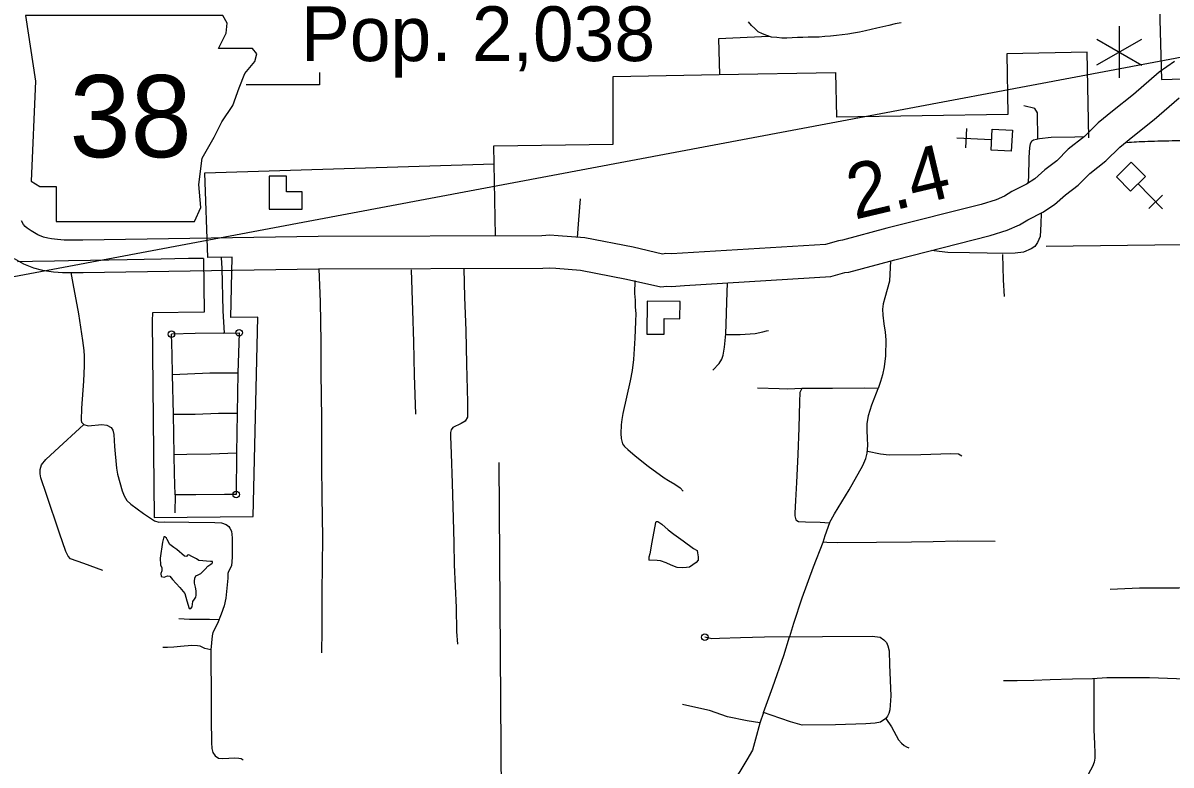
# Model space of a CAD drawing. Extents: x 1367863 to 1368197, y 380048 to 380261.
# Drawn here: x 1367977.76 to 1368012.13, y 380109.23 to 380131.45 of the extents above; entities that cross this region are included whole.
import ezdxf

# ---------------------------------------------------------------- set-up
doc = ezdxf.new("R2010")
doc.units = 0
for name, color, linetype in [('Level 10', 7, 'Continuous'), ('Level 21', 7, 'Continuous'), ('Level 31', 7, 'Continuous'), ('Level 32', 7, 'Continuous'), ('Level 33', 7, 'Continuous'), ('Level 35', 7, 'Continuous'), ('Level 45', 7, 'Continuous'), ('Level 48', 7, 'Continuous'), ('Level 5', 7, 'Continuous'), ('Level 57', 7, 'Continuous'), ('Level 58', 7, 'Continuous'), ('Level 6', 7, 'Continuous'), ('R_Draft', 7, 'Continuous')]:
    doc.layers.add(name, color=color, linetype=linetype)

msp = doc.modelspace()

# ---------------------------------------------------------------- linework, layer by layer
at = {"layer": 'Level 10'}
for points in [[(1368011.429, 380151.098), (1368011.439, 380145.66), (1368011.416, 380141.25), (1368011.392, 380140.52), (1368011.431, 380140.222), (1368011.504, 380139.453), (1368011.603, 380138.92), (1368011.693, 380137.345), (1368011.778, 380132.275), (1368011.845, 380129.756)], [(1368012.237, 380130.295), (1368011.777, 380129.977), (1368011.011, 380129.309), (1368010.379, 380128.804), (1368009.956, 380128.455), (1368009.541, 380128.054), (1368009.05, 380127.67), (1368008.714, 380127.325), (1368008.357, 380127.056), (1368008.052, 380126.787), (1368007.803, 380126.619), (1368007.369, 380126.4), (1368007.149, 380126.265), (1368006.894, 380126.155), (1368006.45, 380126.016), (1368003.623, 380125.301), (1368002.292, 380124.945), (1368002.173, 380124.93), (1368001.785, 380124.821), (1367997.501, 380124.556), (1367997.172, 380124.536), (1367997.008, 380124.543), (1367996.908, 380124.532), (1367996.024, 380124.733), (1367994.579, 380125.013), (1367993.778, 380125.078), (1367993.53, 380125.093), (1367993.289, 380125.078), (1367986.594, 380125.055), (1367979.548, 380124.948)], [(1368011.845, 380129.756), (1368012.815, 380129.782)], [(1367979.555, 380123.978), (1367986.603, 380124.084), (1367993.322, 380124.108), (1367993.531, 380124.121), (1367993.709, 380124.11), (1367994.447, 380124.05), (1367995.825, 380123.783), (1367996.853, 380123.55), (1367997.039, 380123.571), (1367997.179, 380123.564), (1367997.561, 380123.588), (1368001.948, 380123.859), (1368002.368, 380123.977), (1368002.481, 380123.991), (1368003.867, 380124.362), (1368006.714, 380125.082), (1368007.231, 380125.244), (1368007.597, 380125.401), (1368007.842, 380125.552), (1368008.295, 380125.78), (1368008.647, 380126.018), (1368008.97, 380126.304), (1368009.357, 380126.594), (1368009.7, 380126.946), (1368010.179, 380127.321), (1368010.603, 380127.731), (1368010.991, 380128.051), (1368011.633, 380128.564), (1368012.373, 380129.209)], [(1367979.548, 380124.948), (1367979.056, 380124.944), (1367978.988, 380124.946), (1367978.886, 380124.952), (1367978.787, 380124.962), (1367978.613, 380124.986), (1367978.505, 380125.007), (1367978.372, 380125.039), (1367978.201, 380125.109), (1367978.003, 380125.223), (1367977.88, 380125.306), (1367977.822, 380125.354), (1367977.772, 380125.411), (1367977.71, 380125.521)], [(1367977.49, 380124.399), (1367977.773, 380124.236), (1367978.071, 380124.114), (1367978.299, 380124.058), (1367978.456, 380124.029), (1367978.674, 380123.998), (1367978.81, 380123.985), (1367978.944, 380123.977), (1367979.046, 380123.974), (1367979.555, 380123.978)]]:
    msp.add_lwpolyline(points, dxfattribs=at)
at = {"layer": 'Level 21'}
msp.add_lwpolyline([(1367977.833, 380131.673), (1367978.129, 380129.704), (1367977.998, 380126.716), (1367978.26, 380126.552), (1367978.753, 380126.552), (1367978.753, 380125.501), (1367982.889, 380125.501), (1367983.086, 380125.928), (1367983.02, 380126.618), (1367983.119, 380127.405), (1367983.48, 380128.029), (1367983.71, 380128.489), (1367984.038, 380128.981), (1367984.235, 380129.507), (1367984.399, 380129.933), (1367984.695, 380130.294), (1367984.76, 380130.524), (1367984.629, 380130.688), (1367983.611, 380130.688), (1367983.841, 380131.148), (1367983.874, 380131.444), (1367983.738, 380131.67)], close=True, dxfattribs=at)
at = {"layer": 'Level 31'}
for points in [[(1368008.15, 380127.984), (1368008.132, 380128.757), (1368008.054, 380128.887), (1368007.725, 380128.965)], [(1368009.527, 380128.043), (1368009.255, 380128.034), (1368008.544, 380128.021), (1368008.195, 380127.985), (1368008.014, 380127.937), (1368007.96, 380127.901), (1368007.912, 380127.829), (1368007.894, 380127.72), (1368007.876, 380127.419), (1368007.87, 380126.834), (1368007.849, 380126.642)], [(1368010.811, 380127.873), (1368010.881, 380127.878), (1368010.954, 380127.883), (1368011.029, 380127.887), (1368011.104, 380127.892), (1368011.181, 380127.897), (1368011.262, 380127.901), (1368011.348, 380127.905), (1368011.44, 380127.909), (1368011.536, 380127.911), (1368011.637, 380127.914), (1368011.743, 380127.918), (1368011.85, 380127.919), (1368011.958, 380127.922), (1368012.065, 380127.924), (1368012.163, 380127.927), (1368012.241, 380127.93), (1368012.29, 380127.93), (1368012.378, 380127.931), (1368012.429, 380127.932), (1368012.441, 380127.932)], [(1368008.247, 380125.756), (1368008.234, 380125.44), (1368008.218, 380125.054), (1368008.138, 380124.872), (1368008.052, 380124.754), (1368007.945, 380124.689), (1368007.714, 380124.587), (1368007.462, 380124.555), (1368007.082, 380124.55), (1368006.626, 380124.555), (1368006.101, 380124.571), (1368005.447, 380124.577), (1368005.195, 380124.609), (1368004.974, 380124.642)], [(1368003.738, 380124.327), (1368003.704, 380123.717), (1368003.559, 380123.217), (1368003.511, 380123.036), (1368003.493, 380122.885), (1368003.499, 380122.698), (1368003.535, 380122.445), (1368003.577, 380122.192), (1368003.589, 380121.963), (1368003.583, 380121.487), (1368003.541, 380121.159), (1368003.493, 380120.912), (1368003.439, 380120.713), (1368003.36, 380120.502)], [(1367979.579, 380119.425), (1367979.517, 380119.492), (1367979.51, 380119.562), (1367979.517, 380119.918), (1367979.579, 380120.721), (1367979.6, 380121.189), (1367979.6, 380121.475), (1367979.593, 380121.642), (1367979.552, 380121.943), (1367979.433, 380122.745), (1367979.258, 380123.646), (1367979.196, 380123.975)], [(1367986.71, 380112.589), (1367986.719, 380113.269), (1367986.719, 380114.397), (1367986.737, 380116.034), (1367986.719, 380117.287), (1367986.71, 380118.186), (1367986.71, 380119.609), (1367986.683, 380120.978), (1367986.683, 380121.897), (1367986.665, 380123.096), (1367986.63, 380124.085)], [(1367989.382, 380124.059), (1367989.418, 380122.838), (1367989.454, 380121.899), (1367989.472, 380120.905), (1367989.508, 380119.733)], [(1367990.958, 380124.099), (1367990.976, 380123.243), (1367991.021, 380122.241), (1367991.039, 380121.238), (1367991.066, 380120.093)], [(1367996.075, 380123.735), (1367996.068, 380123.35), (1367996.086, 380123.148), (1367996.091, 380122.943), (1367996.109, 380122.75), (1367996.095, 380122.513), (1367996.082, 380122.016), (1367996.037, 380121.377), (1367996.001, 380121.044), (1367995.934, 380120.739), (1367995.831, 380120.247), (1367995.715, 380119.755), (1367995.684, 380119.576), (1367995.67, 380119.419), (1367995.661, 380119.155), (1367995.67, 380119.008), (1367995.706, 380118.851), (1367995.764, 380118.771), (1367995.867, 380118.681), (1367996.086, 380118.487), (1367996.475, 380118.182), (1367996.954, 380117.829), (1367997.083, 380117.757), (1367997.28, 380117.641), (1367997.432, 380117.529), (1367997.522, 380117.435)], [(1367998.411, 380121.059), (1367998.599, 380121.252), (1367998.679, 380121.381), (1367998.724, 380121.507), (1367998.76, 380121.744), (1367998.8, 380122.142), (1367998.809, 380122.437), (1367998.831, 380123.086), (1367998.848, 380123.667)], [(1367998.798, 380122.125), (1367999.234, 380122.124), (1367999.685, 380122.151), (1367999.913, 380122.2), (1368000.016, 380122.231), (1368000.083, 380122.24)], [(1368003.36, 380120.502), (1368002.964, 380120.515), (1368002.001, 380120.502), (1368001.079, 380120.502), (1368000.657, 380120.49), (1368000.398, 380120.496), (1367999.748, 380120.515)], [(1368001.079, 380120.502), (1368001.019, 380120.388), (1368001.007, 380120.111), (1368000.989, 380119.333), (1368000.958, 380118.529), (1368000.922, 380117.691), (1368000.892, 380117.155), (1368000.868, 380116.775), (1368000.868, 380116.691), (1368000.898, 380116.576), (1368000.983, 380116.528), (1368001.187, 380116.516), (1368001.627, 380116.504), (1368001.904, 380116.48)], [(1368001.904, 380116.48), (1368002.061, 380116.751), (1368002.495, 380117.474), (1368002.91, 380118.203), (1368002.995, 380118.408), (1368003.031, 380118.571), (1368003.055, 380118.8), (1368003.043, 380119.023), (1368003.031, 380119.252), (1368003.037, 380119.451), (1368003.079, 380119.698), (1368003.175, 380120.017), (1368003.314, 380120.379), (1368003.36, 380120.502)], [(1367991.066, 380120.093), (1367991.066, 380119.649), (1367990.994, 380119.524), (1367990.878, 380119.461), (1367990.628, 380119.336), (1367990.583, 380119.273), (1367990.556, 380119.193), (1367990.556, 380119.076), (1367990.574, 380118.548), (1367990.61, 380117.671), (1367990.637, 380116.624), (1367990.655, 380115.887), (1367990.663, 380115.225), (1367990.726, 380113.954), (1367990.735, 380113.229), (1367990.771, 380112.849)], [(1367980.152, 380115.062), (1367979.579, 380115.272), (1367979.182, 380115.404), (1367979.105, 380115.488), (1367979.042, 380115.628), (1367978.847, 380116.172), (1367978.463, 380117.331), (1367978.295, 380117.827), (1367978.274, 380117.952), (1367978.274, 380118.078), (1367978.309, 380118.218), (1367978.442, 380118.385), (1367978.84, 380118.748), (1367979.447, 380119.307), (1367979.579, 380119.425)], [(1367979.579, 380119.425), (1367979.712, 380119.391), (1367980.117, 380119.425), (1367980.263, 380119.405), (1367980.396, 380119.342), (1367980.452, 380119.258), (1367980.48, 380119.132), (1367980.494, 380118.769), (1367980.556, 380118.12), (1367980.591, 380117.939), (1367980.731, 380117.443), (1367980.787, 380117.296), (1367980.863, 380117.15), (1367980.989, 380117.045), (1367981.366, 380116.766), (1367981.694, 380116.542), (1367981.826, 380116.5), (1367982.008, 380116.514), (1367982.727, 380116.507), (1367983.501, 380116.493), (1367983.697, 380116.48), (1367983.836, 380116.431), (1367983.92, 380116.375), (1367983.955, 380116.326), (1367984.004, 380116.235), (1367984.025, 380116.033), (1367984.025, 380115.809), (1367984.025, 380115.46), (1367983.997, 380115.202), (1367983.913, 380115.027), (1367983.892, 380114.965), (1367983.892, 380114.832), (1367983.829, 380114.225), (1367983.78, 380113.998), (1367983.69, 380113.753), (1367983.585, 380113.467), (1367983.438, 380113.202), (1367983.417, 380113.104), (1367983.397, 380112.888), (1367983.383, 380112.685), (1367983.383, 380112.12), (1367983.39, 380111.68), (1367983.39, 380110.594), (1367983.397, 380109.91), (1367983.411, 380109.728), (1367983.445, 380109.61), (1367983.508, 380109.512), (1367983.613, 380109.435), (1367983.745, 380109.428), (1367984.101, 380109.449), (1367984.22, 380109.442), (1367984.29, 380109.428), (1367984.346, 380109.386)], [(1368003.045, 380118.629), (1368003.436, 380118.554), (1368003.698, 380118.524), (1368004.638, 380118.534), (1368005.54, 380118.563), (1368005.772, 380118.554), (1368005.869, 380118.495)], [(1368001.904, 380116.48), (1368001.772, 380116.093), (1368001.705, 380115.9), (1368001.422, 380115.153), (1368001.079, 380114.231), (1368000.832, 380113.471), (1368000.705, 380113.068)], [(1368006.868, 380115.926), (1368005.736, 380115.932), (1368005.012, 380115.921), (1368004.36, 380115.91), (1368003.311, 380115.893), (1368002.151, 380115.882), (1368001.825, 380115.899), (1368001.708, 380115.907)], [(1367983.627, 380113.583), (1367983.345, 380113.59), (1367982.741, 380113.59), (1367982.426, 380113.609)], [(1367983.383, 380112.684), (1367983.198, 380112.72), (1367983.063, 380112.788), (1367982.986, 380112.806), (1367982.812, 380112.809), (1367982.472, 380112.785), (1367982.276, 380112.766), (1367982.083, 380112.748), (1367981.997, 380112.751), (1367981.942, 380112.751)], [(1368000.705, 380113.068), (1367999.965, 380113.062), (1367999.242, 380113.038), (1367998.609, 380113.019), (1367998.38, 380113.013), (1367998.175, 380113.062)], [(1368000.705, 380113.068), (1368001.693, 380113.082), (1368003.181, 380113.088), (1368003.422, 380113.058), (1368003.531, 380112.986), (1368003.615, 380112.901), (1368003.651, 380112.805), (1368003.693, 380112.654), (1368003.705, 380112.232), (1368003.742, 380111.304), (1368003.711, 380110.888), (1368003.687, 380110.78), (1368003.645, 380110.696), (1368003.591, 380110.623), (1368003.434, 380110.515), (1368003.278, 380110.485), (1368002.995, 380110.467), (1368002.085, 380110.437), (1368001.091, 380110.431), (1368000.742, 380110.527), (1368000.163, 380110.726), (1367999.928, 380110.81)], [(1367999.928, 380110.81), (1368000.212, 380111.575), (1368000.537, 380112.51), (1368000.705, 380113.068)], [(1368012.71, 380111.809), (1368012.297, 380111.815), (1368011.493, 380111.841), (1368010.759, 380111.848), (1368010.211, 380111.841), (1368009.78, 380111.815), (1368009.181, 380111.803), (1368008.518, 380111.783), (1368008.029, 380111.764), (1368007.526, 380111.751), (1368007.114, 380111.757)], [(1368009.818, 380111.818), (1368009.818, 380111.406), (1368009.825, 380110.775), (1368009.818, 380110.292), (1368009.838, 380109.867), (1368009.854, 380109.593), (1368009.851, 380109.444), (1368009.83, 380109.319), (1368009.778, 380109.188), (1368009.667, 380108.969), (1368009.58, 380108.744), (1368009.567, 380108.633), (1368009.56, 380108.401), (1368009.577, 380107.794), (1368009.572, 380107.131), (1368009.576, 380106.139)], [(1367999.928, 380110.81), (1367999.82, 380110.491), (1367999.687, 380110.009), (1367999.597, 380109.677), (1367999.428, 380109.388), (1367999.224, 380109.044), (1367999.103, 380108.864), (1367998.989, 380108.743), (1367998.724, 380108.526), (1367998.38, 380108.165), (1367998.091, 380107.853), (1367997.669, 380107.353), (1367997.332, 380107.058), (1367996.784, 380106.594), (1367996.2, 380106.118), (1367995.712, 380105.72), (1367995.296, 380105.383), (1367994.923, 380105.069), (1367994.814, 380104.955), (1367994.67, 380104.732), (1367994.543, 380104.509), (1367994.423, 380104.252), (1367994.32, 380104.053)], [(1368003.591, 380110.623), (1368003.761, 380110.373), (1368003.977, 380109.988), (1368004.065, 380109.886), (1368004.146, 380109.819), (1368004.214, 380109.775), (1368004.285, 380109.748)]]:
    msp.add_lwpolyline(points, dxfattribs=at)
msp.add_circle((1367998.175, 380113.062), 0.097, dxfattribs=at)
at = {"layer": 'Level 32'}
for points in [[(1367994.44, 380126.181), (1367994.392, 380125.556), (1367994.35, 380125.031)], [(1368007.085, 380124.516), (1368007.106, 380123.755), (1368007.133, 380123.262)], [(1367999.821, 380110.494), (1367999.44, 380110.561), (1367998.856, 380110.682), (1367998.314, 380110.862), (1367997.633, 380111.019), (1367997.501, 380111.049)]]:
    msp.add_lwpolyline(points, dxfattribs=at)
at = {"layer": 'Level 33'}
for points in [[(1368004.05, 380131.455), (1368003.871, 380131.421), (1368003.688, 380131.373), (1368003.507, 380131.332), (1368003.328, 380131.289), (1368003.151, 380131.252), (1368002.98, 380131.209), (1368002.804, 380131.176), (1368002.629, 380131.145), (1368002.456, 380131.116), (1368002.284, 380131.092), (1368002.112, 380131.07), (1368001.941, 380131.051), (1368001.768, 380131.039), (1368001.598, 380131.028), (1368001.431, 380131.022), (1368001.266, 380131.022), (1368001.104, 380131.01), (1368000.947, 380131.009), (1368000.787, 380131.001), (1368000.626, 380130.998), (1368000.475, 380130.989), (1368000.326, 380131.009), (1368000.17, 380131.024), (1368000.032, 380131.069), (1367999.899, 380131.121), (1367999.774, 380131.188), (1367999.676, 380131.279), (1367999.571, 380131.374), (1367999.479, 380131.481)], [(1367983.787, 380122.167), (1367983.75, 380122.829), (1367983.725, 380124.108), (1367983.701, 380124.413)], [(1367983.758, 380122.167), (1367982.908, 380122.149), (1367982.201, 380122.131)], [(1367982.309, 380117.326), (1367982.291, 380117.961), (1367982.282, 380118.516), (1367982.273, 380119.142), (1367982.264, 380119.733), (1367982.237, 380120.914), (1367982.228, 380121.531), (1367982.201, 380122.131)], [(1367983.758, 380122.167), (1367984.232, 380122.176)], [(1367984.232, 380122.176), (1367984.187, 380120.968), (1367984.169, 380119.769), (1367984.151, 380118.569), (1367984.142, 380117.335)], [(1367984.187, 380120.968), (1367983.355, 380120.968), (1367982.237, 380120.914)], [(1367982.264, 380119.733), (1367982.908, 380119.742), (1367983.615, 380119.769), (1367984.169, 380119.769)], [(1367984.151, 380118.569), (1367983.382, 380118.543), (1367982.666, 380118.534), (1367982.282, 380118.516)], [(1367982.309, 380117.326), (1367982.3, 380116.78)], [(1367984.142, 380117.335), (1367983.794, 380117.335), (1367982.935, 380117.326), (1367982.309, 380117.326)]]:
    msp.add_lwpolyline(points, dxfattribs=at)
for centre in [(1367982.201, 380122.131), (1367984.232, 380122.176), (1367984.142, 380117.335)]:
    msp.add_circle(centre, 0.097, dxfattribs=at)
at = {"layer": 'Level 35'}
for points in [[(1367996.698, 380116.496), (1367996.723, 380116.521), (1367996.764, 380116.526), (1367996.885, 380116.445), (1367997.072, 380116.278), (1367997.25, 380116.142), (1367997.528, 380115.944), (1367997.837, 380115.721), (1367997.948, 380115.656), (1367997.958, 380115.585), (1367997.978, 380115.463), (1367997.978, 380115.372), (1367997.913, 380115.296), (1367997.816, 380115.23), (1367997.71, 380115.159), (1367997.629, 380115.144), (1367997.518, 380115.134), (1367997.341, 380115.149), (1367997.169, 380115.22), (1367997.012, 380115.291), (1367996.85, 380115.347), (1367996.744, 380115.357), (1367996.501, 380115.372)], [(1367996.698, 380116.496), (1367996.587, 380115.909), (1367996.526, 380115.559), (1367996.501, 380115.453), (1367996.501, 380115.372)], [(1367983.369, 380115.327), (1367983.02, 380115.36), (1367982.954, 380115.409), (1367982.81, 380115.474), (1367982.727, 380115.529), (1367982.685, 380115.512), (1367982.65, 380115.477), (1367982.598, 380115.491), (1367982.367, 380115.69), (1367982.27, 380115.742), (1367982.154, 380115.84), (1367982.071, 380115.987), (1367982.05, 380116.028), (1367982.008, 380116.063), (1367981.977, 380116.07), (1367981.935, 380115.906), (1367981.865, 380115.428), (1367981.872, 380115.226), (1367981.914, 380115.138), (1367981.91, 380115.051), (1367981.889, 380114.971), (1367981.893, 380114.88), (1367981.98, 380114.859), (1367982.081, 380114.894), (1367982.151, 380114.884), (1367982.238, 380114.789), (1367982.451, 380114.552), (1367982.605, 380114.371), (1367982.664, 380114.151), (1367982.737, 380113.924), (1367982.783, 380113.924), (1367982.824, 380113.966), (1367982.828, 380114.046), (1367982.845, 380114.13), (1367982.891, 380114.203), (1367982.929, 380114.255), (1367982.94, 380114.318), (1367982.94, 380114.447), (1367982.926, 380114.556), (1367982.894, 380114.674), (1367982.891, 380114.741), (1367982.901, 380114.824), (1367982.933, 380114.894), (1367982.999, 380114.929), (1367983.086, 380114.971), (1367983.138, 380115.023), (1367983.159, 380115.044), (1367983.215, 380115.1), (1367983.292, 380115.184), (1367983.379, 380115.25), (1367983.425, 380115.278), (1367983.435, 380115.302), (1367983.428, 380115.327), (1367983.411, 380115.327), (1367983.369, 380115.327)]]:
    msp.add_lwpolyline(points, dxfattribs=at)
at = {"layer": 'Level 45'}
msp.add_lwpolyline([(1368012.66, 380114.555), (1368012.369, 380114.524), (1368011.194, 380114.524), (1368010.313, 380114.492)], dxfattribs=at)
at = {"layer": 'Level 48'}
for p, q in [((1368010.584, 380131.355), (1368010.582, 380129.802)), ((1368009.91, 380130.192), (1368011.256, 380130.966)), ((1368009.911, 380130.968), (1368011.255, 380130.189))]:
    msp.add_line(p, q, dxfattribs=at)
at = {"layer": 'Level 5'}
for points in [[(1367991.905, 380125.073), (1367991.866, 380127.227)], [(1368008.395, 380124.769), (1368012.457, 380124.82)], [(1367992.115, 380104.055), (1367992.012, 380118.293)]]:
    msp.add_lwpolyline(points, dxfattribs=at)
at = {"layer": 'Level 57'}
for p, q in [((1368005.994, 380127.707), (1368006.024, 380128.288)), ((1368005.718, 380128.013), (1368006.762, 380127.959)), ((1368011.878, 380125.887), (1368011.145, 380126.631)), ((1368011.881, 380126.298), (1368011.467, 380125.89))]:
    msp.add_line(p, q, dxfattribs=at)
for points in [[(1368007.351, 380127.614), (1368006.746, 380127.645), (1368006.778, 380128.272), (1368007.383, 380128.241)], [(1368010.945, 380127.284), (1368011.37, 380126.853), (1368010.922, 380126.412), (1368010.497, 380126.843)]]:
    msp.add_lwpolyline(points, close=True, dxfattribs=at)
at = {"layer": 'Level 58'}
for points in [[(1367985.126, 380125.873), (1367986.112, 380125.873), (1367986.112, 380126.394), (1367985.645, 380126.394), (1367985.645, 380126.859), (1367985.126, 380126.859)], [(1367996.445, 380123.123), (1367996.435, 380122.137), (1367996.955, 380122.132), (1367996.96, 380122.598), (1367997.426, 380122.594), (1367997.431, 380123.113)]]:
    msp.add_lwpolyline(points, close=True, dxfattribs=at)
at = {"layer": 'Level 6'}
for p, q in [((1367995.428, 380129.846), (1367998.602, 380129.906)), ((1367995.43, 380127.824), (1367995.428, 380129.846)), ((1367991.857, 380127.767), (1367995.43, 380127.824)), ((1367991.866, 380127.227), (1367991.857, 380127.767)), ((1367983.204, 380126.967), (1367991.866, 380127.227))]:
    msp.add_line(p, q, dxfattribs=at)
for points in [[(1368000.094, 380131.048), (1367998.585, 380130.971)], [(1368000.094, 380131.048), (1367998.585, 380130.971)], [(1367998.585, 380130.971), (1367998.61, 380129.906)], [(1367998.585, 380130.971), (1367998.61, 380129.906)], [(1368009.618, 380130.572), (1368007.216, 380130.52)], [(1368007.216, 380130.52), (1368007.245, 380128.707)], [(1368009.672, 380128.014), (1368009.618, 380130.572)], [(1367998.602, 380129.906), (1368002.088, 380129.971)], [(1368002.088, 380129.971), (1368002.12, 380128.626)], [(1367986.634, 380129.968), (1367986.638, 380129.594), (1367984.437, 380129.595)], [(1368007.245, 380128.707), (1368002.12, 380128.626)], [(1367984.018, 380124.434), (1367983.295, 380124.426), (1367983.204, 380126.967)], [(1367983.164, 380124.401), (1367982.713, 380124.393), (1367981.893, 380124.377), (1367980.878, 380124.359), (1367979.776, 380124.338), (1367979.121, 380124.326), (1367978.702, 380124.318), (1367978.037, 380124.306), (1367977.589, 380124.298)], [(1367981.634, 380122.769), (1367981.622, 380122.534), (1367981.688, 380116.649), (1367984.654, 380116.677), (1367984.791, 380122.641), (1367983.976, 380122.628), (1367984.018, 380124.434)], [(1367983.164, 380124.401), (1367983.182, 380122.789), (1367981.634, 380122.769), (1367981.634, 380122.769)]]:
    msp.add_lwpolyline(points, dxfattribs=at)
at = {"layer": 'R_Draft'}
msp.add_lwpolyline([(1368027.28, 380133.22), (1367942.971, 380117.362)], dxfattribs=at)

# ---------------------------------------------------------------- texts
at = {"layer": 'Level 21'}
msp.add_text('38', height=2.459, dxfattribs=at).set_placement((1367979.15, 380127.43))
at = {"layer": 'Level 48'}
msp.add_text('2.4', height=1.6394, rotation=13.3362, dxfattribs=at).set_placement((1368002.657, 380125.556))
at = {"layer": 'Level 6'}
msp.add_text('Pop. 2,038', height=1.6394, dxfattribs=at).set_placement((1367986.08, 380130.307))

doc.saveas('drawing.dxf')
